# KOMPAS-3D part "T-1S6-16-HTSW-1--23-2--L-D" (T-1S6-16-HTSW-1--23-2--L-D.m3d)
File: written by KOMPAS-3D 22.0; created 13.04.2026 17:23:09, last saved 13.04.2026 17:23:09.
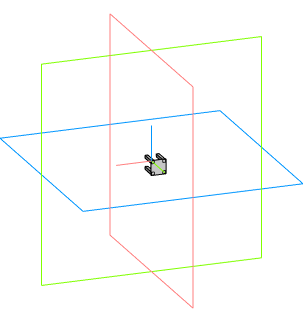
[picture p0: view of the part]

Document properties: Автор: Andrey; Полное имя файла: C:\Users\User1\Documents\T-1S6-16-HTSW-1--23-2--L-D.m3d

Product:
- Part/product: T-1S6-16-HTSW-1--23-2--L-D
    Комментарий: T-1S6-16-HTSW-1--23-2--L-D

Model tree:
1. Операция без истории:1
